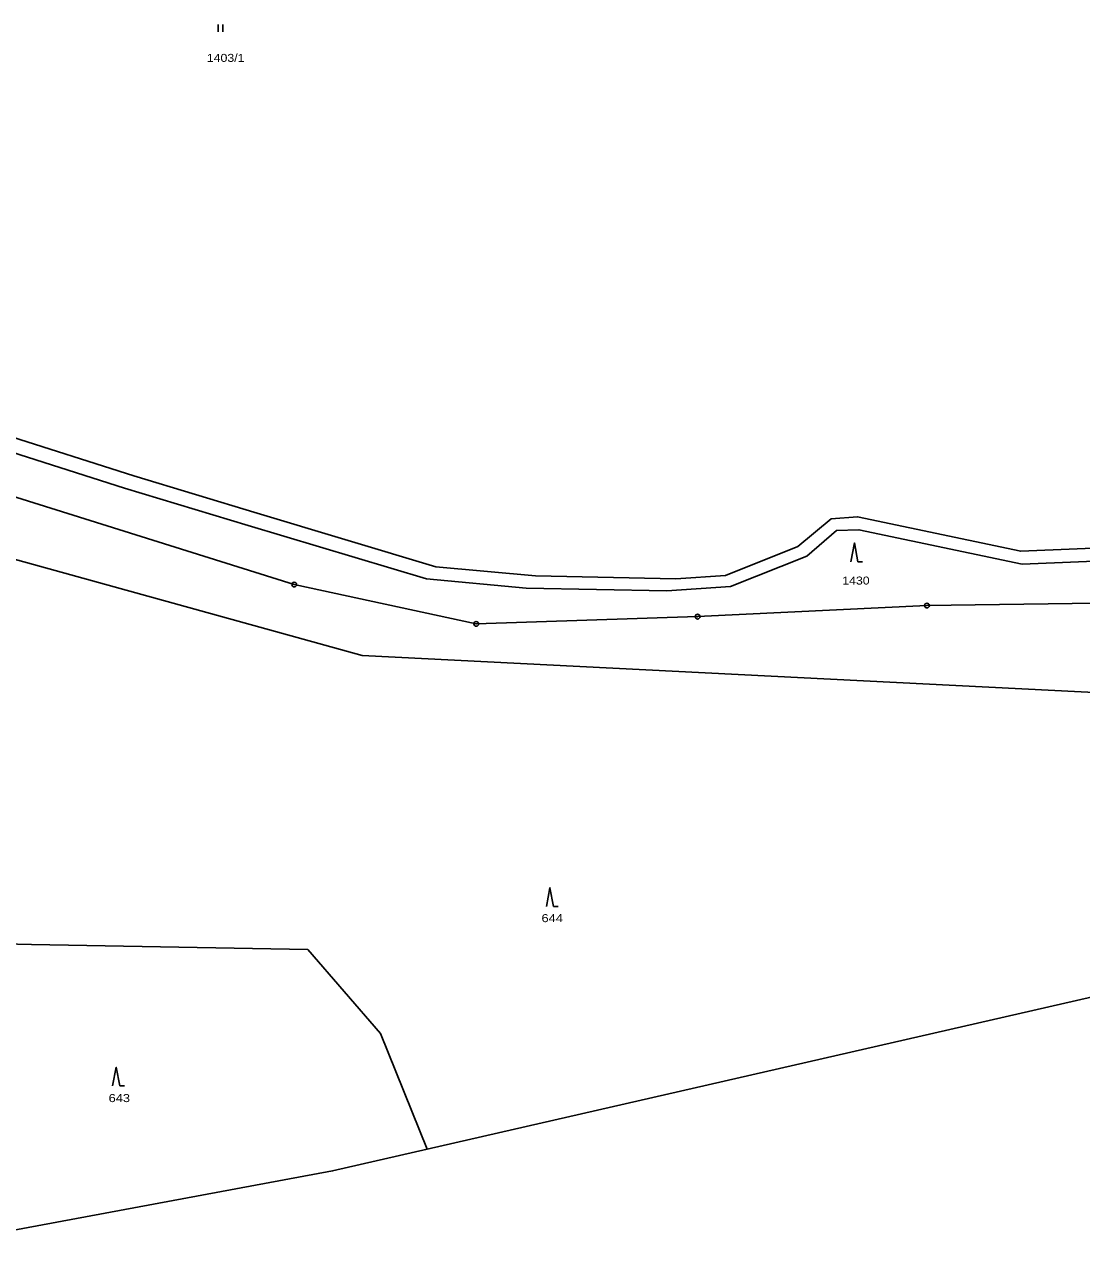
# Model space of a CAD drawing. Extents: x -872229 to -869198, y -1075981 to -1074329.
# Drawn here: x -870264.6 to -870040, y -1075773.8 to -1075512.3 of the extents above; entities that cross this region are included whole.
import ezdxf

# ---------------------------------------------------------------- set-up
doc = ezdxf.new("R2010")
doc.units = 0
doc.header["$LTSCALE"] = 0.68
for name, color, linetype, lineweight in [('1', 7, 'Continuous', 25), ('3', 7, 'Continuous', 25), ('8', 7, 'Continuous', 25)]:
    doc.layers.add(name, color=color, linetype=linetype, lineweight=lineweight)
doc.layers.add('2', color=7, linetype='Continuous')

msp = doc.modelspace()

# ---------------------------------------------------------------- linework, layer by layer
at = {"layer": '1'}
for points in [[(-870360.91, -1075564.7), (-870334.21, -1075571.6), (-870312.37, -1075586.81), (-870293.77, -1075595.76), (-870270.86, -1075602.02), (-870243.34, -1075610.77), (-870217.09, -1075618.71), (-870179.15, -1075630.08), (-870157.97, -1075632.03), (-870128.13, -1075632.63), (-870114.57, -1075631.72), (-870098.39, -1075625.25), (-870092.04, -1075619.77), (-870087.29, -1075619.63), (-870052.6, -1075626.97), (-870018.4, -1075625.53), (-869988.87, -1075627.77), (-869967.84, -1075631.16), (-869962.49, -1075632.97), (-869956.97, -1075636.94), (-869956.21, -1075634.42)], [(-869956.21, -1075634.42), (-869961.39, -1075630.69), (-869968.14, -1075628.41), (-869989.17, -1075625.02), (-870018.7, -1075622.78), (-870052.9, -1075624.22), (-870087.59, -1075616.88), (-870093.16, -1075617.33), (-870100.3, -1075623.21), (-870115.61, -1075629.33), (-870126.17, -1075630.04), (-870156.01, -1075629.44), (-870177.19, -1075627.49), (-870215.13, -1075616.12), (-870241.38, -1075608.18), (-870268.9, -1075599.43), (-870291.81, -1075593.17), (-870310.41, -1075584.22), (-870332.25, -1075569.01)], [(-870319.49, -1075589.3), (-870295.19, -1075603.73), (-870207.28, -1075631.27), (-870168.61, -1075639.64), (-870121.56, -1075638.1), (-870072.83, -1075635.74), (-870016.23, -1075634.96), (-869958.54, -1075642.14), (-869957.53, -1075638.79), (-869956.97, -1075636.94)], [(-869946.97, -1075719.04), (-869951.52, -1075667.78), (-870006.44, -1075655.77), (-870192.84, -1075646.38), (-870362.26, -1075599.45), (-870356.17, -1075620.52)], [(-870179.01, -1075751.24), (-870188.98, -1075726.65), (-870204.4, -1075708.79), (-870263.11, -1075707.73), (-870292.9, -1075707.03), (-870321.66, -1075708.31)], [(-870179.01, -1075751.24), (-870035.17, -1075718.28), (-870015.01, -1075718.11)], [(-870295.8, -1075773.81), (-870199.13, -1075755.85), (-870179.01, -1075751.24)]]:
    msp.add_lwpolyline(points, dxfattribs=at)
at = {"layer": '3'}
for p, q in [((-870223.461, -1075513.81), (-870223.461, -1075512.31)), ((-870222.46, -1075513.81), (-870222.46, -1075512.31)), ((-870087.51, -1075626.42), (-870086.514, -1075626.42)), ((-870152.21, -1075699.71), (-870151.214, -1075699.71)), ((-870244.36, -1075737.82), (-870243.364, -1075737.82))]:
    msp.add_line(p, q, dxfattribs=at)
for points in [[(-870087.51, -1075626.42), (-870088.26, -1075622.42), (-870089.01, -1075626.42)], [(-870152.21, -1075699.71), (-870152.96, -1075695.71), (-870153.71, -1075699.71)], [(-870244.36, -1075737.82), (-870245.11, -1075733.82), (-870245.86, -1075737.82)]]:
    msp.add_lwpolyline(points, dxfattribs=at)
at = {"layer": '8'}
for centre, radius in [((-870207.28, -1075631.2699), 0.5), ((-870207.28, -1075631.2699), 0.0303), ((-870072.83, -1075635.7399), 0.5), ((-870072.83, -1075635.7399), 0.0303), ((-870121.56, -1075638.0999), 0.5), ((-870121.56, -1075638.0999), 0.0303), ((-870168.61, -1075639.6399), 0.5), ((-870168.61, -1075639.6399), 0.0303)]:
    msp.add_circle(centre, radius, dxfattribs=at)

# ---------------------------------------------------------------- texts
at = {"layer": '2'}
for s, width, p in [('1403/1', 1.15, (-870225.85, -1075520.23)), ('1430', 1.15, (-870090.83, -1075631.28)), ('644', 1.2, (-870154.74, -1075703.01)), ('643', 1.2, (-870246.72, -1075741.24))]:
    msp.add_text(s, height=1.7, dxfattribs=dict(at, width=width)).set_placement(p)

doc.saveas('drawing.dxf')
